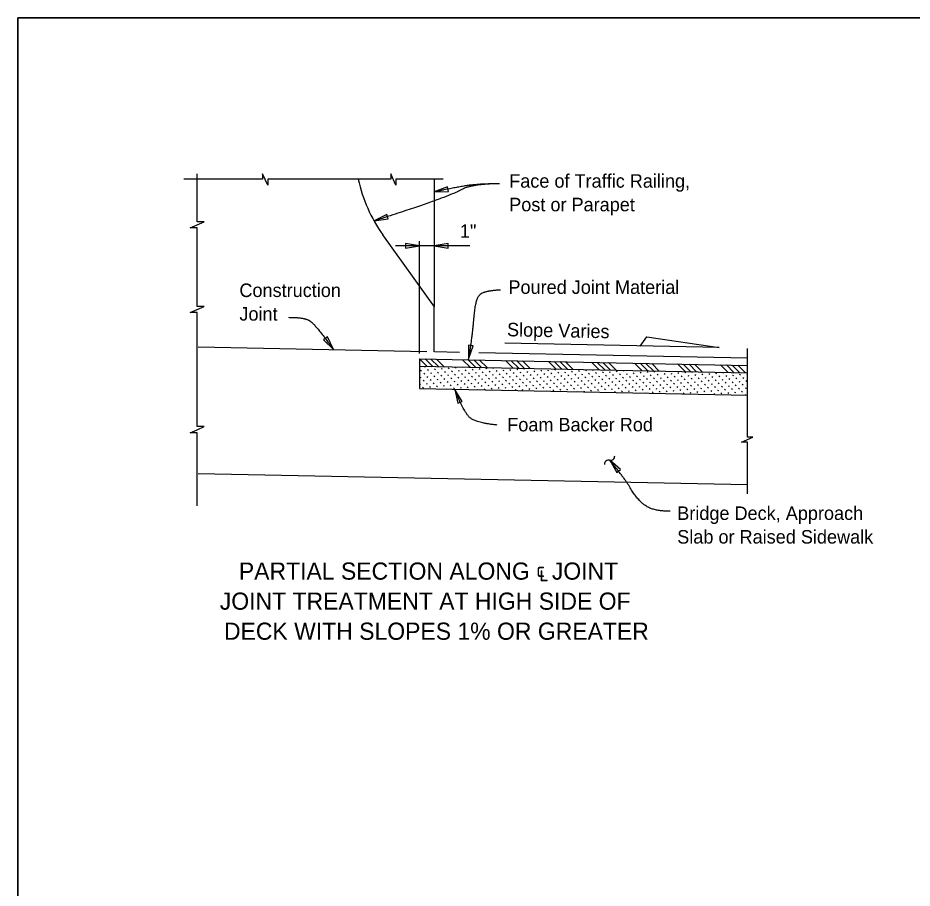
# Model space of a CAD drawing. Extents: x 0 to 15.4, y 0 to 9.7.
# Drawn here: x 0 to 5, y 4.865 to 9.73 of the extents above; entities that cross this region are included whole.
import ezdxf

# ---------------------------------------------------------------- set-up
doc = ezdxf.new("R2010")
doc.units = 0
for name, color, linetype in [('Dimension', 7, 'Continuous'), ('Miscellaneous', 7, 'Continuous'), ('Miscellaneous1', 7, 'Continuous'), ('SupstrConc', 7, 'Continuous'), ('SupstrConc_h', 7, 'Continuous'), ('TextStructures', 7, 'Continuous')]:
    doc.layers.add(name, color=color, linetype=linetype)

msp = doc.modelspace()

# ---------------------------------------------------------------- linework, layer by layer
at = {"layer": 'Dimension'}
for p, q in [((2.5267, 8.4554), (2.1107, 8.4554)), ((2.245, 7.8533), (2.245, 8.4812))]:
    msp.add_line(p, q, dxfattribs=at)
for points in [[(1.5891, 8.8277), (1.3965, 8.8277), (1.3965, 8.7947), (1.3681, 8.8587), (1.3681, 8.8277), (0.9287, 8.8277)], [(1.0021, 8.1468), (1.0021, 8.5563), (0.9633, 8.5563), (1.0021, 8.5732), (1.0408, 8.59), (1.0021, 8.59), (1.0021, 8.8574)], [(2.3781, 8.8277), (2.1137, 8.8277), (2.1137, 8.7947), (2.0854, 8.8587), (2.0854, 8.8277), (1.5891, 8.8277)], [(1.0021, 7.8056), (1.0021, 8.0825), (0.9633, 8.0825), (1.0021, 8.0994), (1.0408, 8.1163), (1.0021, 8.1163), (1.0021, 8.4259)], [(3.4799, 7.8946), (3.5164, 7.947), (3.9199, 7.8871), (2.7233, 7.911)], [(4.0784, 7.07), (4.0784, 7.3582), (4.0453, 7.3582), (4.1093, 7.3865), (4.0784, 7.3865), (4.0784, 7.8815)], [(1.0021, 7.0013), (1.0021, 7.4109), (0.9633, 7.4109), (1.0021, 7.4277), (1.0408, 7.4446), (1.0021, 7.4446), (1.0021, 7.8056)]]:
    msp.add_lwpolyline(points, dxfattribs=at)
for points in [[(2.3282, 8.7569), (2.4074, 8.76), (2.402, 8.7859)], [(1.9921, 8.5944), (2.0705, 8.6058), (2.0623, 8.631)], [(2.2449, 8.4555), (2.1668, 8.4687), (2.1668, 8.4423)], [(2.3283, 8.4555), (2.4064, 8.4423), (2.4064, 8.4687)], [(1.765, 7.8751), (1.7301, 7.9462), (1.7086, 7.9307)], [(2.5186, 7.8213), (2.5445, 7.8961), (2.5184, 7.9005)], [(2.4425, 7.6531), (2.459, 7.5756), (2.4836, 7.5854)], [(3.3086, 7.2571), (3.3484, 7.1886), (3.3688, 7.2055)]]:
    msp.add_lwpolyline(points, close=True, dxfattribs=at)
for centre, start, end in [((3.3024, 7.2354), 74.5069, 186.2341), ((3.3143, 7.2785), 254.5069, 6.2341)]:
    msp.add_arc(centre, 0.0224, start, end, dxfattribs=at)
for points in [[(2.6928, 8.8022), (2.5341, 8.8022), (2.4132, 8.7304), (1.9921, 8.5944)], [(2.6928, 8.8022), (2.5757, 8.8022), (2.4453, 8.7815), (2.3282, 8.7569)], [(2.6983, 8.2079), (2.6269, 8.2054), (2.558, 8.1734), (2.5408, 7.9543), (2.5186, 7.8213)], [(1.5127, 8.0558), (1.6022, 8.0558), (1.663, 8.0165), (1.765, 7.875)], [(2.6789, 7.4537), (2.5533, 7.466), (2.4893, 7.5349), (2.4426, 7.6531)], [(3.6467, 6.9718), (3.5504, 6.9718), (3.4616, 7.0379), (3.3936, 7.1551), (3.3086, 7.2571)]]:
    msp.add_open_spline(points, degree=2, dxfattribs=at)
at = {"layer": 'Miscellaneous'}
for p, q in [((2.245, 7.8238), (2.245, 7.6571)), ((2.245, 7.8238), (4.0784, 7.7871)), ((2.245, 7.8238), (2.2875, 7.7813)), ((2.2768, 7.8232), (2.3194, 7.7806)), ((2.3087, 7.8225), (2.3512, 7.78)), ((2.3405, 7.8219), (2.3831, 7.7793)), ((2.4856, 7.819), (2.5281, 7.7764)), ((2.5174, 7.8184), (2.56, 7.7758)), ((2.5492, 7.8177), (2.5918, 7.7752)), ((2.5811, 7.8171), (2.6236, 7.7745)), ((2.7262, 7.8142), (2.7687, 7.7716)), ((2.758, 7.8135), (2.8006, 7.771)), ((2.7898, 7.8129), (2.8324, 7.7703)), ((2.8217, 7.8123), (2.8642, 7.7697)), ((2.9668, 7.8094), (3.0093, 7.7668)), ((2.9986, 7.8087), (3.0412, 7.7662)), ((3.0304, 7.8081), (3.073, 7.7655)), ((3.0623, 7.8075), (3.1048, 7.7649)), ((3.2073, 7.8046), (3.2499, 7.762)), ((3.2392, 7.8039), (3.2817, 7.7614)), ((3.271, 7.8033), (3.3136, 7.7607)), ((3.3029, 7.8026), (3.3454, 7.7601)), ((3.4479, 7.7997), (3.4905, 7.7572)), ((2.245, 7.7821), (4.0784, 7.7454)), ((2.2535, 7.7556), (2.2567, 7.7612)), ((2.2744, 7.7765), (2.2773, 7.7815)), ((2.2921, 7.7588), (2.2954, 7.7644)), ((2.3131, 7.7798), (2.3137, 7.7807)), ((2.3308, 7.762), (2.334, 7.7676)), ((2.3485, 7.7443), (2.3518, 7.7499)), ((2.3695, 7.7653), (2.3727, 7.7709)), ((2.3872, 7.7476), (2.3904, 7.7532)), ((2.4081, 7.7685), (2.4114, 7.7741)), ((2.4259, 7.7508), (2.4291, 7.7564)), ((2.4468, 7.7718), (2.4501, 7.7774)), ((2.4645, 7.7541), (2.4678, 7.7597)), ((2.4855, 7.775), (2.4868, 7.7773)), ((2.5032, 7.7573), (2.5064, 7.7629)), ((2.5419, 7.7605), (2.5451, 7.7661)), ((2.5805, 7.7638), (2.5838, 7.7694)), ((2.5983, 7.7461), (2.6015, 7.7517)), ((2.6192, 7.767), (2.6225, 7.7726)), ((2.6369, 7.7493), (2.6402, 7.7549)), ((2.6579, 7.7703), (2.6599, 7.7738)), ((2.6756, 7.7525), (2.6788, 7.7581)), ((2.7143, 7.7558), (2.7175, 7.7614)), ((2.7529, 7.759), (2.7562, 7.7646)), ((2.7916, 7.7623), (2.7948, 7.7679)), ((2.8093, 7.7446), (2.8126, 7.7502)), ((2.8303, 7.7655), (2.8331, 7.7703)), ((2.848, 7.7478), (2.8512, 7.7534)), ((2.8689, 7.7688), (2.8694, 7.7696)), ((2.8867, 7.751), (2.8899, 7.7566)), ((2.9253, 7.7543), (2.9286, 7.7599)), ((2.964, 7.7575), (2.9672, 7.7631)), ((3.0027, 7.7608), (3.0059, 7.7664)), ((3.0413, 7.764), (3.0426, 7.7661)), ((3.0591, 7.7463), (3.0623, 7.7519)), ((3.0977, 7.7495), (3.101, 7.7551)), ((3.1364, 7.7528), (3.1396, 7.7584)), ((3.1751, 7.756), (3.1783, 7.7616)), ((3.2137, 7.7593), (3.2157, 7.7627)), ((3.2701, 7.7448), (3.2734, 7.7504)), ((3.3088, 7.748), (3.312, 7.7536)), ((3.3475, 7.7513), (3.3507, 7.7569)), ((3.3861, 7.7545), (3.3889, 7.7592)), ((3.4248, 7.7577), (3.4252, 7.7585)), ((3.4798, 7.7991), (3.5223, 7.7565)), ((3.5116, 7.7985), (3.5542, 7.7559)), ((3.5199, 7.7465), (3.5231, 7.7521)), ((3.5435, 7.7978), (3.586, 7.7553)), ((3.5585, 7.7497), (3.5618, 7.7553)), ((3.5972, 7.753), (3.5984, 7.755)), ((3.6885, 7.7949), (3.7311, 7.7524)), ((3.7204, 7.7943), (3.7629, 7.7517)), ((3.7309, 7.745), (3.7342, 7.7506)), ((3.7522, 7.7936), (3.7948, 7.7511)), ((3.7696, 7.7482), (3.7715, 7.7516)), ((3.784, 7.793), (3.8266, 7.7504)), ((3.9291, 7.7901), (3.9717, 7.7475)), ((3.961, 7.7895), (4.0035, 7.7469)), ((3.9928, 7.7888), (4.0354, 7.7463)), ((4.0246, 7.7882), (4.0672, 7.7456)), ((2.2502, 7.7169), (2.2535, 7.7225)), ((2.2679, 7.6992), (2.2712, 7.7048)), ((2.2712, 7.7379), (2.2744, 7.7435)), ((2.2889, 7.7201), (2.2921, 7.7257)), ((2.3066, 7.7024), (2.3099, 7.708)), ((2.3099, 7.7411), (2.3131, 7.7467)), ((2.3276, 7.7234), (2.3308, 7.729)), ((2.3453, 7.7057), (2.3485, 7.7113)), ((2.3662, 7.7266), (2.3695, 7.7322)), ((2.384, 7.7089), (2.3872, 7.7145)), ((2.4049, 7.7299), (2.4081, 7.7355)), ((2.4226, 7.7121), (2.4259, 7.7177)), ((2.4403, 7.6944), (2.4436, 7.7)), ((2.4436, 7.7331), (2.4468, 7.7387)), ((2.4613, 7.7154), (2.4645, 7.721)), ((2.479, 7.6977), (2.4822, 7.7033)), ((2.4822, 7.7363), (2.4855, 7.7419)), ((2.5, 7.7186), (2.5032, 7.7242)), ((2.5177, 7.7009), (2.5209, 7.7065)), ((2.5209, 7.7396), (2.5242, 7.7452)), ((2.5386, 7.7219), (2.5419, 7.7275)), ((2.5563, 7.7042), (2.5596, 7.7098)), ((2.5596, 7.7428), (2.5628, 7.7484)), ((2.5773, 7.7251), (2.5805, 7.7307)), ((2.595, 7.7074), (2.5983, 7.713)), ((2.616, 7.7284), (2.6192, 7.7339)), ((2.6337, 7.7106), (2.6369, 7.7162)), ((2.6546, 7.7316), (2.6579, 7.7372)), ((2.6724, 7.7139), (2.6756, 7.7195)), ((2.6901, 7.6962), (2.6933, 7.7018)), ((2.6933, 7.7348), (2.6966, 7.7404)), ((2.711, 7.7171), (2.7143, 7.7227)), ((2.7287, 7.6994), (2.732, 7.705)), ((2.732, 7.7381), (2.7352, 7.7437)), ((2.7497, 7.7204), (2.7529, 7.726)), ((2.7674, 7.7026), (2.7707, 7.7082)), ((2.7707, 7.7413), (2.7739, 7.7469)), ((2.7884, 7.7236), (2.7916, 7.7292)), ((2.8061, 7.7059), (2.8093, 7.7115)), ((2.827, 7.7268), (2.8303, 7.7324)), ((2.8448, 7.7091), (2.848, 7.7147)), ((2.8657, 7.7301), (2.8689, 7.7357)), ((2.8834, 7.7124), (2.8867, 7.718)), ((2.9011, 7.6947), (2.9044, 7.7003)), ((2.9044, 7.7333), (2.9076, 7.7389)), ((2.9221, 7.7156), (2.9253, 7.7212)), ((2.9398, 7.6979), (2.943, 7.7035)), ((2.943, 7.7366), (2.9463, 7.7422)), ((2.9608, 7.7188), (2.964, 7.7244)), ((2.9785, 7.7011), (2.9817, 7.7067)), ((2.9817, 7.7398), (2.985, 7.7454)), ((2.9994, 7.7221), (3.0027, 7.7277)), ((3.0171, 7.7044), (3.0204, 7.71)), ((3.0204, 7.743), (3.0236, 7.7486)), ((3.0381, 7.7253), (3.0413, 7.7309)), ((3.0558, 7.7076), (3.0591, 7.7132)), ((3.0768, 7.7286), (3.08, 7.7342)), ((3.0945, 7.7109), (3.0977, 7.7165)), ((3.1154, 7.7318), (3.1187, 7.7374)), ((3.1332, 7.7141), (3.1364, 7.7197)), ((3.1509, 7.6964), (3.1541, 7.702)), ((3.1541, 7.7351), (3.1574, 7.7407)), ((3.1718, 7.7173), (3.1751, 7.7229)), ((3.1895, 7.6996), (3.1928, 7.7052)), ((3.1928, 7.7383), (3.196, 7.7439)), ((3.2105, 7.7206), (3.2137, 7.7262)), ((3.2282, 7.7029), (3.2314, 7.7085)), ((3.2314, 7.7415), (3.2347, 7.7471)), ((3.2492, 7.7238), (3.2524, 7.7294)), ((3.2669, 7.7061), (3.2701, 7.7117)), ((3.2878, 7.7271), (3.2911, 7.7327)), ((3.3055, 7.7093), (3.3088, 7.7149)), ((3.3265, 7.7303), (3.3297, 7.7359)), ((3.3442, 7.7126), (3.3475, 7.7182)), ((3.3619, 7.6949), (3.3652, 7.7005)), ((3.3652, 7.7335), (3.3684, 7.7391)), ((3.3829, 7.7158), (3.3861, 7.7214)), ((3.4006, 7.6981), (3.4038, 7.7037)), ((3.4038, 7.7368), (3.4071, 7.7424)), ((3.4216, 7.7191), (3.4248, 7.7247)), ((3.4393, 7.7014), (3.4425, 7.707)), ((3.4425, 7.74), (3.4458, 7.7456)), ((3.4602, 7.7223), (3.4635, 7.7279)), ((3.4779, 7.7046), (3.4812, 7.7102)), ((3.4812, 7.7433), (3.4844, 7.7489)), ((3.4989, 7.7256), (3.5021, 7.7312)), ((3.5166, 7.7078), (3.5199, 7.7134)), ((3.5376, 7.7288), (3.5408, 7.7344)), ((3.5553, 7.7111), (3.5585, 7.7167)), ((3.5762, 7.732), (3.5795, 7.7376)), ((3.594, 7.7143), (3.5972, 7.7199)), ((3.6117, 7.6966), (3.6149, 7.7022)), ((3.6149, 7.7353), (3.6181, 7.7409)), ((3.6326, 7.7176), (3.6359, 7.7232)), ((3.6503, 7.6998), (3.6536, 7.7054)), ((3.6536, 7.7385), (3.6568, 7.7441)), ((3.6713, 7.7208), (3.6745, 7.7264)), ((3.689, 7.7031), (3.6922, 7.7087)), ((3.6922, 7.7418), (3.6955, 7.7474)), ((3.71, 7.724), (3.7132, 7.7296)), ((3.7277, 7.7063), (3.7309, 7.7119)), ((3.7486, 7.7273), (3.7519, 7.7329)), ((3.7663, 7.7096), (3.7696, 7.7152)), ((3.7873, 7.7305), (3.7905, 7.7361)), ((3.805, 7.7128), (3.8083, 7.7184)), ((3.8227, 7.6951), (3.826, 7.7007)), ((3.826, 7.7338), (3.8292, 7.7394)), ((3.8437, 7.7161), (3.8469, 7.7216)), ((3.8614, 7.6983), (3.8646, 7.7039)), ((3.8646, 7.737), (3.8679, 7.7426)), ((3.8824, 7.7193), (3.8856, 7.7249)), ((3.9001, 7.7016), (3.9033, 7.7072)), ((3.9033, 7.7402), (3.9066, 7.7458)), ((3.921, 7.7225), (3.9243, 7.7281)), ((3.9387, 7.7048), (3.942, 7.7104)), ((3.942, 7.7435), (3.9446, 7.7481)), ((3.9597, 7.7258), (3.9629, 7.7314)), ((3.9774, 7.7081), (3.9807, 7.7137)), ((3.9807, 7.7467), (3.981, 7.7474)), ((3.9984, 7.729), (4.0016, 7.7346)), ((4.0161, 7.7113), (4.0193, 7.7169)), ((4.037, 7.7323), (4.0403, 7.7379)), ((4.0547, 7.7145), (4.058, 7.7201)), ((4.0725, 7.6968), (4.0757, 7.7024)), ((4.0757, 7.7355), (4.0784, 7.7402)), ((2.245, 7.6571), (4.0784, 7.6204)), ((2.247, 7.6782), (2.2502, 7.6838)), ((2.2647, 7.6605), (2.2679, 7.6661)), ((2.2857, 7.6815), (2.2889, 7.6871)), ((2.3034, 7.6638), (2.3066, 7.6694)), ((2.3243, 7.6847), (2.3276, 7.6903)), ((2.342, 7.667), (2.3453, 7.6726)), ((2.3629, 7.6547), (2.363, 7.6549)), ((2.363, 7.688), (2.3662, 7.6935)), ((2.3807, 7.6702), (2.384, 7.6758)), ((2.3993, 7.654), (2.4017, 7.6581)), ((2.4017, 7.6912), (2.4049, 7.6968)), ((2.4194, 7.6735), (2.4226, 7.6791)), ((2.4371, 7.6558), (2.4403, 7.6614)), ((2.4581, 7.6767), (2.4613, 7.6823)), ((2.4758, 7.659), (2.479, 7.6646)), ((2.4967, 7.68), (2.5, 7.6856)), ((2.5144, 7.6622), (2.5177, 7.6678)), ((2.5354, 7.6832), (2.5386, 7.6888)), ((2.5531, 7.6655), (2.5563, 7.6711)), ((2.5724, 7.6505), (2.5741, 7.6534)), ((2.5741, 7.6864), (2.5773, 7.692)), ((2.5918, 7.6687), (2.595, 7.6743)), ((2.6095, 7.651), (2.6127, 7.6566)), ((2.6127, 7.6897), (2.616, 7.6953)), ((2.6304, 7.672), (2.6337, 7.6776)), ((2.6482, 7.6543), (2.6514, 7.6599)), ((2.6514, 7.6929), (2.6546, 7.6985)), ((2.6691, 7.6752), (2.6724, 7.6808)), ((2.6868, 7.6575), (2.6901, 7.6631)), ((2.7078, 7.6784), (2.711, 7.684)), ((2.7255, 7.6607), (2.7287, 7.6663)), ((2.7465, 7.6817), (2.7497, 7.6873)), ((2.7642, 7.664), (2.7674, 7.6696)), ((2.7819, 7.6463), (2.7851, 7.6519)), ((2.7851, 7.6849), (2.7884, 7.6905)), ((2.8028, 7.6672), (2.8061, 7.6728)), ((2.8206, 7.6495), (2.8238, 7.6551)), ((2.8238, 7.6882), (2.827, 7.6938)), ((2.8415, 7.6705), (2.8448, 7.6761)), ((2.8592, 7.6527), (2.8625, 7.6583)), ((2.8625, 7.6914), (2.8657, 7.697)), ((2.8802, 7.6737), (2.8834, 7.6793)), ((2.8979, 7.656), (2.9011, 7.6616)), ((2.9188, 7.6769), (2.9221, 7.6825)), ((2.9366, 7.6592), (2.9398, 7.6648)), ((2.9575, 7.6802), (2.9608, 7.6858)), ((2.9752, 7.6625), (2.9785, 7.6681)), ((2.9929, 7.6448), (2.9962, 7.6503)), ((2.9962, 7.6834), (2.9994, 7.689)), ((3.0139, 7.6657), (3.0171, 7.6713)), ((3.0316, 7.648), (3.0349, 7.6536)), ((3.0349, 7.6867), (3.0381, 7.6923)), ((3.0526, 7.6689), (3.0558, 7.6745)), ((3.0703, 7.6512), (3.0735, 7.6568)), ((3.0735, 7.6899), (3.0768, 7.6955)), ((3.0912, 7.6722), (3.0945, 7.6778)), ((3.109, 7.6545), (3.1122, 7.6601)), ((3.1122, 7.6931), (3.1154, 7.6987)), ((3.1299, 7.6754), (3.1332, 7.681)), ((3.1476, 7.6577), (3.1509, 7.6633)), ((3.1686, 7.6787), (3.1718, 7.6843)), ((3.1863, 7.661), (3.1895, 7.6666)), ((3.2073, 7.6819), (3.2105, 7.6875)), ((3.225, 7.6642), (3.2282, 7.6698)), ((3.2427, 7.6465), (3.2459, 7.6521)), ((3.2459, 7.6852), (3.2492, 7.6907)), ((3.2636, 7.6674), (3.2669, 7.673)), ((3.2814, 7.6497), (3.2846, 7.6553)), ((3.2846, 7.6884), (3.2878, 7.694)), ((3.3023, 7.6707), (3.3055, 7.6763)), ((3.32, 7.653), (3.3233, 7.6586)), ((3.3233, 7.6916), (3.3265, 7.6972)), ((3.341, 7.6739), (3.3442, 7.6795)), ((3.3587, 7.6562), (3.3619, 7.6618)), ((3.3796, 7.6772), (3.3829, 7.6828)), ((3.3974, 7.6594), (3.4006, 7.665)), ((3.4183, 7.6804), (3.4216, 7.686)), ((3.436, 7.6627), (3.4393, 7.6683)), ((3.4537, 7.645), (3.457, 7.6506)), ((3.457, 7.6836), (3.4602, 7.6892)), ((3.4747, 7.6659), (3.4779, 7.6715)), ((3.4924, 7.6482), (3.4957, 7.6538)), ((3.4957, 7.6869), (3.4989, 7.6925)), ((3.5134, 7.6692), (3.5166, 7.6748)), ((3.5311, 7.6515), (3.5343, 7.6571)), ((3.5343, 7.6901), (3.5376, 7.6957)), ((3.552, 7.6724), (3.5553, 7.678)), ((3.5698, 7.6547), (3.573, 7.6603)), ((3.573, 7.6934), (3.5762, 7.699)), ((3.5907, 7.6756), (3.594, 7.6812)), ((3.6084, 7.6579), (3.6117, 7.6635)), ((3.6294, 7.6789), (3.6326, 7.6845)), ((3.6471, 7.6612), (3.6503, 7.6668)), ((3.6681, 7.6821), (3.6713, 7.6877)), ((3.6858, 7.6644), (3.689, 7.67)), ((3.7035, 7.6467), (3.7067, 7.6523)), ((3.7067, 7.6854), (3.71, 7.691)), ((3.7244, 7.6677), (3.7277, 7.6733)), ((3.7421, 7.6499), (3.7454, 7.6555)), ((3.7454, 7.6886), (3.7486, 7.6942)), ((3.7631, 7.6709), (3.7663, 7.6765)), ((3.7808, 7.6532), (3.7841, 7.6588)), ((3.7841, 7.6919), (3.7873, 7.6975)), ((3.8018, 7.6741), (3.805, 7.6797)), ((3.8195, 7.6564), (3.8227, 7.662)), ((3.8404, 7.6774), (3.8437, 7.683)), ((3.8582, 7.6597), (3.8614, 7.6653)), ((3.8791, 7.6806), (3.8824, 7.6862)), ((3.8968, 7.6629), (3.9001, 7.6685)), ((3.9145, 7.6452), (3.9178, 7.6508)), ((3.9178, 7.6839), (3.921, 7.6895)), ((3.9355, 7.6661), (3.9387, 7.6717)), ((3.9532, 7.6484), (3.9565, 7.654)), ((3.9565, 7.6871), (3.9597, 7.6927)), ((3.9742, 7.6694), (3.9774, 7.675)), ((3.9919, 7.6517), (3.9951, 7.6573)), ((3.9951, 7.6903), (3.9984, 7.6959)), ((4.0128, 7.6726), (4.0161, 7.6782)), ((4.0306, 7.6549), (4.0338, 7.6605)), ((4.0338, 7.6936), (4.037, 7.6992)), ((4.0515, 7.6759), (4.0547, 7.6815)), ((4.0692, 7.6582), (4.0725, 7.6638)), ((2.7456, 7.6471), (2.7465, 7.6486)), ((2.9187, 7.6436), (2.9188, 7.6439)), ((2.9551, 7.6429), (2.9575, 7.6471)), ((3.1282, 7.6394), (3.1299, 7.6424)), ((3.1653, 7.64), (3.1686, 7.6456)), ((3.204, 7.6432), (3.2073, 7.6488)), ((3.3013, 7.6359), (3.3023, 7.6376)), ((3.3377, 7.6352), (3.341, 7.6408)), ((3.3764, 7.6385), (3.3796, 7.6441)), ((3.4151, 7.6417), (3.4183, 7.6473)), ((3.4745, 7.6325), (3.4747, 7.6329)), ((3.5109, 7.6317), (3.5134, 7.6361)), ((3.5488, 7.6337), (3.552, 7.6393)), ((3.5875, 7.637), (3.5907, 7.6426)), ((3.6261, 7.6402), (3.6294, 7.6458)), ((3.6648, 7.6435), (3.6681, 7.6491)), ((3.684, 7.6283), (3.6858, 7.6313)), ((3.7212, 7.629), (3.7244, 7.6346)), ((3.7599, 7.6322), (3.7631, 7.6378)), ((3.7985, 7.6355), (3.8018, 7.6411)), ((3.8372, 7.6387), (3.8404, 7.6443)), ((3.8571, 7.6248), (3.8582, 7.6266)), ((3.8759, 7.642), (3.8791, 7.6475)), ((3.8936, 7.6242), (3.8968, 7.6298)), ((3.9323, 7.6275), (3.9355, 7.6331)), ((3.9709, 7.6307), (3.9742, 7.6363)), ((4.0096, 7.634), (4.0128, 7.6396)), ((4.0303, 7.6213), (4.0306, 7.6218)), ((4.0483, 7.6372), (4.0515, 7.6428)), ((4.0666, 7.6206), (4.0692, 7.6251))]:
    msp.add_line(p, q, dxfattribs=at)
msp.add_lwpolyline([(0, 0), (15.394, 0), (15.394, 9.7298), (0, 9.7298)], close=True, dxfattribs=at)
at = {"layer": 'Miscellaneous1'}
msp.add_lwpolyline([(0, 9.7298), (15.394, 9.7298), (15.394, 0), (0, 0)], close=True, dxfattribs=at)
at = {"layer": 'SupstrConc'}
for p, q in [((2.3284, 8.1137), (2.3284, 8.8277)), ((2.3284, 8.1137), (2.0401, 8.5173)), ((2.3283, 7.8638), (2.3283, 8.1138)), ((2.3284, 7.8639), (2.4691, 7.861)), ((2.5771, 7.8589), (4.0784, 7.8288)), ((1.0079, 7.1819), (4.0784, 7.1205))]:
    msp.add_line(p, q, dxfattribs=at)
msp.add_arc((2.7181, 9.0017), 0.8333, 192.0469, 215.5377, dxfattribs=at)
at = {"layer": 'SupstrConc_h'}
msp.add_line((1.0081, 7.8902), (2.2867, 7.8646), dxfattribs=at)

# ---------------------------------------------------------------- texts
at = {"layer": 'Dimension'}
for s, height, p in [('Face of Traffic Railing, ', 0.0756, (2.7469, 8.7805)), ('Post or Parapet', 0.0756, (2.7469, 8.6485)), ('Construction ', 0.0756, (1.2385, 8.1693)), ('Joint', 0.0756, (1.2385, 8.0373)), ('Bridge Deck, Approach ', 0.0756, (3.6863, 6.923)), ('Slab or Raised Sidewalk', 0.0756, (3.6863, 6.791)), ('PARTIAL SECTION ALONG ℄ JOINT', 0.096, (1.2355, 6.5892)), ('JOINT TREATMENT AT HIGH SIDE OF', 0.096, (1.1289, 6.4212)), ('DECK WITH SLOPES 1% OR GREATER', 0.096, (1.1522, 6.2532))]:
    msp.add_text(s, height=height, dxfattribs=at).set_placement(p)
at = {"layer": 'TextStructures'}
for s, p in [('1"', (2.4713, 8.5003)), ('Poured Joint Material', (2.7426, 8.1869)), ('Foam Backer Rod', (2.7359, 7.4183))]:
    msp.add_text(s, height=0.0756, dxfattribs=at).set_placement(p)
msp.add_text('Slope Varies', height=0.0756, rotation=358.8543, dxfattribs=at).set_placement((2.7341, 7.9501))

doc.saveas('drawing.dxf')
